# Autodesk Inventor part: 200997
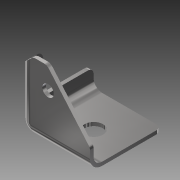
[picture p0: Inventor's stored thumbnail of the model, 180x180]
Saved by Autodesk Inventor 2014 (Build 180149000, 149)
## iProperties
Created: 2007-12
Part Number: 200997
Document SubType Name: Modeling
Designer: MM
Density: 7.85 g/cm^3
Mass: 90.2441 g
Surface Area: 99.9897 cm^2
Volume: 11.4961 cm^3
Material: Steel
Description: CORNER BRACKET
Appearance: Steel - Polished
Component Category: Lower Component
Author: MM
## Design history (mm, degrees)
node "200134" dims "d0" = 10
body "Solid1"
tag "TaggingFeature2"
feature "DerivedBody::D-200134" dims "d0" = 10
